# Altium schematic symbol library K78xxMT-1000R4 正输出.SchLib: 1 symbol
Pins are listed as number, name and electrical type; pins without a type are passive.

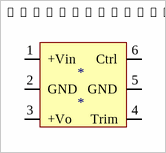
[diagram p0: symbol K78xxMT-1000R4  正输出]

## K78xxMT-1000R4  正输出
designator *
footprint K78xxMT-500R4 正输出
pins: 1 +Vin, 2 GND, 3 +Vo, 4 Trim, 5 GND, 6 Ctrl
